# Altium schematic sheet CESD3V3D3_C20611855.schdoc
size 127 x 101 mm
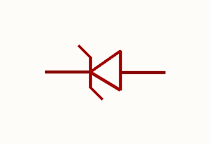
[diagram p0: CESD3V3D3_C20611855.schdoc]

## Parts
D?  cesd3v3d3  [SOD-323_L1.7-W1.3-LS2.5-RD]  (value not drawn)

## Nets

Not connected (* = marked no-connect by the designer): D? 1(C) 2(A)

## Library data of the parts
D? = cesd3v3d3: 反向截止电压(Vrwm):3.3V;钳位电压:15V;峰值脉冲电流(Ipp):10A@8/20us;峰值脉冲功率(Ppp):150W@8/20us;击穿电压:4.8V;; Manufacturer: TECH PUBLIC(台舟); Symbol: CESD3V3D3_C20611855; AddInBom: yes; ModelId: 0f2f330c645944df9245ac3c3fec3456; ModelName: SOD-323_L1.7-W1.3-LS2.5-FD; ModelTransform: 98.425,49.2125,0,0,0,0,0,0,0; Reverse Stand-Off Voltage (Vrwm): 3.3V; Clamping Voltage: 15V; Voltage - Breakdown: 4.8V; Reverse Leakage Current (Ir): 500nA; Number of Channels: 单路; level of protection: IEC 61000-4-5；IEC 61000-4-4；IEC 61000-4-2; Junction Capacitance: 200pF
